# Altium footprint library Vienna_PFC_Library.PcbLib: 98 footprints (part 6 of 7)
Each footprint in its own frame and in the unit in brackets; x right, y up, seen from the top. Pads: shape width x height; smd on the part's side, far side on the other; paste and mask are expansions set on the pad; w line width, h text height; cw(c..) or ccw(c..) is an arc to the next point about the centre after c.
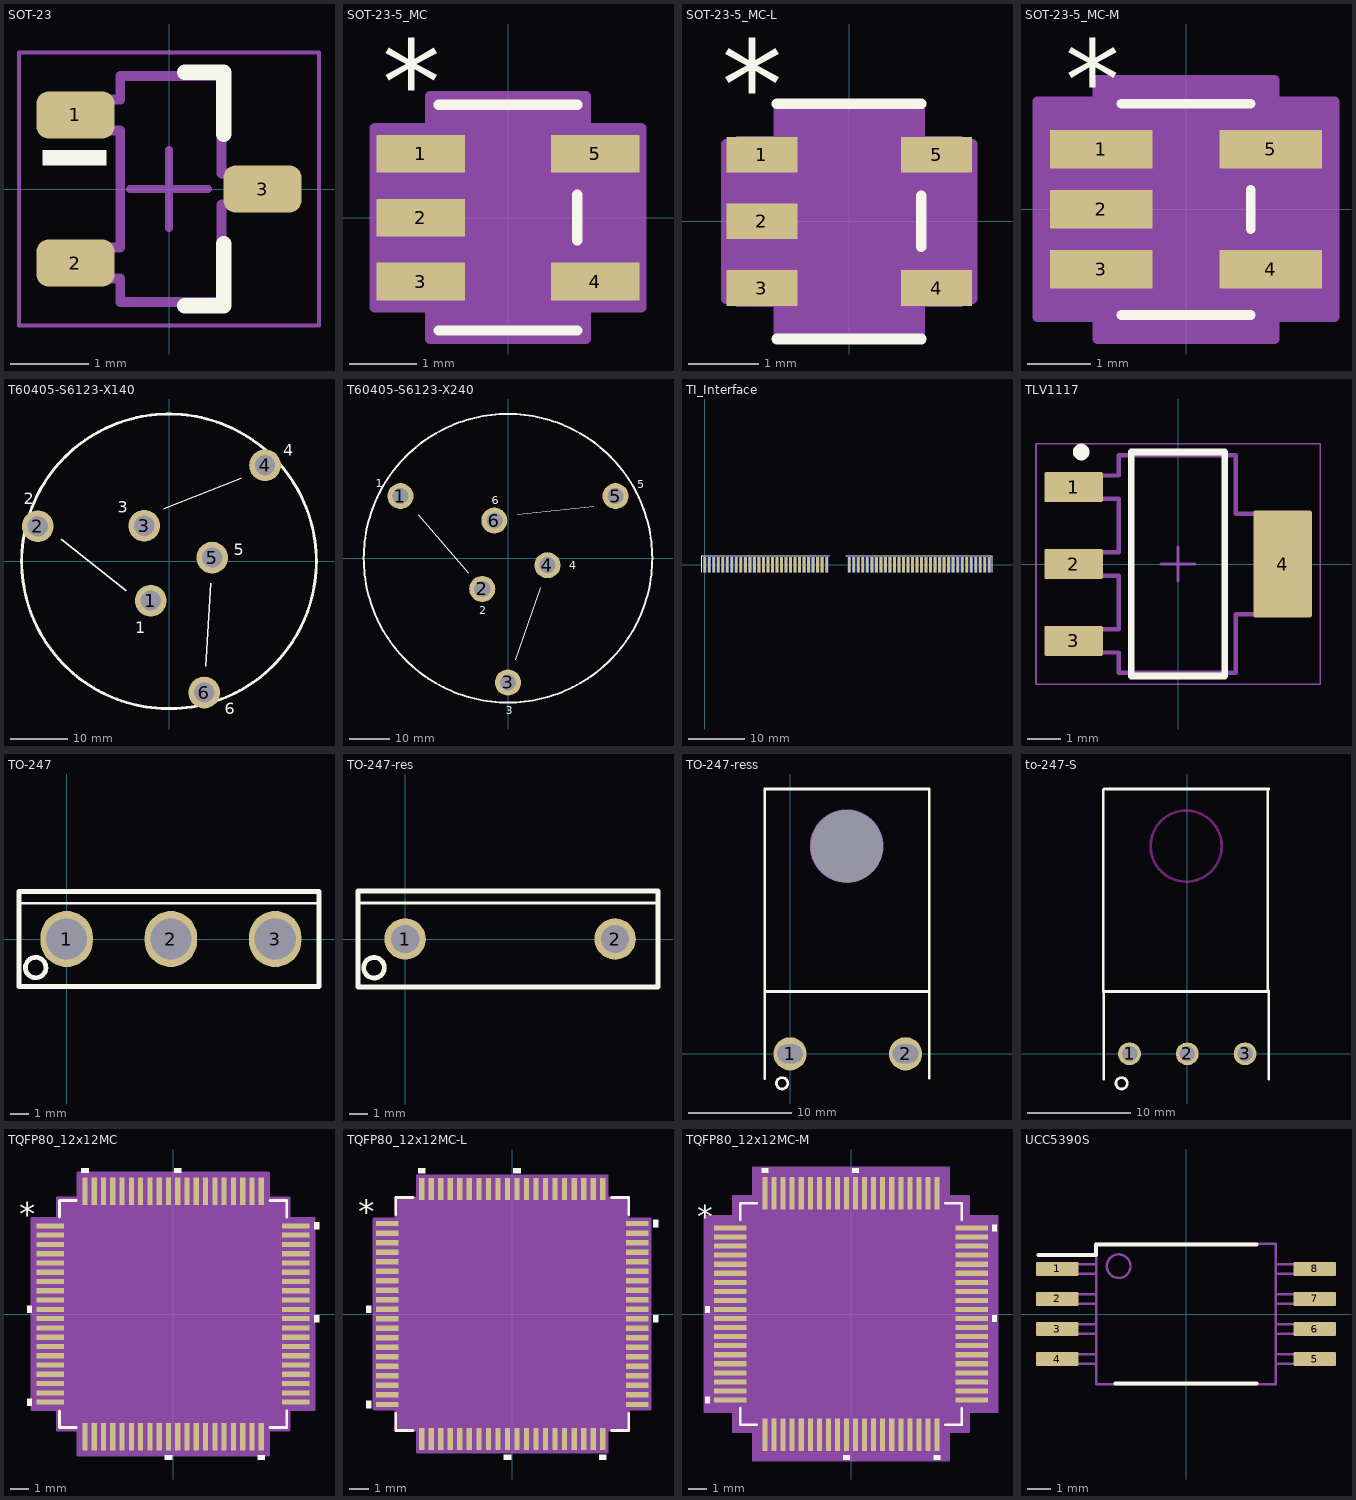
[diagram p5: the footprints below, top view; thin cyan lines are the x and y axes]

## SOT-23 [mm] "SOT23, 3-Leads, Body 2.9x1.3mm, Pitch 0.95mm, Lead Span 2.5mm, IPC Medium Density"
height 1.1
pads (3):
  rrect50% 1x0.6 smd: 1(-1.2,0.95) 2(-1.2,-0.95) 3(1.2,0)
Top Overlay:
  rectangle: -1.625,0.3 -0.8,0.5
  lines w0.2: 0.2,-1.5 0.7,-1.5 0.7,-0.7 ; 0.2,1.5 0.7,1.5 0.7,0.7
Mechanical 5:
  lines w0.127: -1.16,-1.15 -1.16,-0.75 -0.625,-0.75 -0.625,0.75 -1.16,0.75 -1.16,1.15 -0.625,1.15 -0.625,1.45 0.675,1.45 0.675,0.2 1.21,0.2 1.21,-0.2 0.675,-0.2 0.675,-1.45 -0.625,-1.45 -0.625,-1.15 -1.16,-1.15
Mechanical 15:
  lines w0.05: -1.925,-1.75 1.925,-1.75 1.925,1.75 -1.925,1.75 -1.925,-1.75
  lines w0.1: -0.5,0 0.5,0 ; 0,-0.5 0,0.5
3D body "SW3dPS-sot-3p290x130ll237h100.STEP": height 1, standoff 0, extent -1.16,-1.45 1.21,1.45

## SOT-23-5_MC [mil]
pads (5):
  rect 52x22 smd paste+0 mask+0: 1(-51,37.4) 2(-51,0) 3(-51,-37.4) 4(51,-37.4) 5(51,37.4)
Top Overlay:
  lines w6: -40.5,-66 40.5,-66 ; -40.5,66 40.5,66 ; 40.5,-13.3 40.5,13.3
  text "*" at -73.5,54.4 h50
Mechanical 13:
  lines w0: -12,61 ccw(c0,61) 12,61
  lines w1: -63,-47.4 -35.5,-47.4 -35.5,-27.4 -63,-27.4 -63,-47.4 ; -63,-10 -35.5,-10 -35.5,10 -63,10 -63,-10 ; -63,27.4 -35.5,27.4 -35.5,47.4 -63,47.4 -63,27.4 ; -35.5,-61 -35.5,61 35.5,61 35.5,-61 -35.5,-61 ; 35.5,-47.4 63,-47.4 63,-27.4 35.5,-27.4 35.5,-47.4 ; 35.5,27.4 63,27.4 63,47.4 35.5,47.4 35.5,27.4
  text "*" at -38,16.4 h50
Mechanical 15:
  region: 45.5,-71 -45.5,-71 -45.5,-52.4 -78,-52.4 -78,52.4 -45.5,52.4 -45.5,71 45.5,71 45.5,52.4 78,52.4 78,-52.4 45.5,-52.4
  lines w6: -78,-52.4 -78,52.4 -45.5,52.4 -45.5,71 45.5,71 45.5,52.4 78,52.4 78,-52.4 45.5,-52.4 45.5,-71 -45.5,-71 -45.5,-52.4 -78,-52.4
3D body: height 10, standoff 0, extent 0,0 10,10

## SOT-23-5_MC-L [mil]
pads (5):
  rect 40x20 smd paste+0 mask+0: 1(-49,37.4) 2(-49,0) 3(-49,-37.4) 4(49,-37.4) 5(49,37.4)
Top Overlay:
  lines w6: -40.5,-66 40.5,-66 ; -40.5,66 40.5,66 ; 40.5,-14.3 40.5,14.3
  text "*" at -71.5,52.4 h50
Mechanical 13:
  lines w0: -12,61 ccw(c0,61) 12,61
  lines w1: -63,-47.4 -63,-27.4 -35.5,-27.4 -35.5,-47.4 -63,-47.4 ; -63,-10 -63,10 -35.5,10 -35.5,-10 -63,-10 ; -63,27.4 -63,47.4 -35.5,47.4 -35.5,27.4 -63,27.4 ; -35.5,-61 35.5,-61 35.5,61 -35.5,61 -35.5,-61 ; 35.5,-47.4 35.5,-27.4 63,-27.4 63,-47.4 35.5,-47.4 ; 35.5,27.4 35.5,47.4 63,47.4 63,27.4 35.5,27.4
  text "*" at -38,14.4 h50
Mechanical 15:
  region: 39.5,-65 -39.5,-65 -39.5,-43.4 -69,-43.4 -69,43.4 -39.5,43.4 -39.5,65 39.5,65 39.5,43.4 69,43.4 69,-43.4 39.5,-43.4
  lines w6: -69,-43.4 -39.5,-43.4 -39.5,-65 39.5,-65 39.5,-43.4 69,-43.4 69,43.4 39.5,43.4 39.5,65 -39.5,65 -39.5,43.4 -69,43.4 -69,-43.4
3D body: height 10, standoff 0, extent 0,0 10,10

## SOT-23-5_MC-M [mil]
pads (5):
  rect 64x24 smd paste+0 mask+0: 1(-53,37.4) 2(-53,0) 3(-53,-37.4) 4(53,-37.4) 5(53,37.4)
Top Overlay:
  lines w6: -40.5,-66 40.5,-66 ; -40.5,66 40.5,66 ; 40.5,-12.3 40.5,12.3
  text "*" at -75.5,56.4 h50
Mechanical 13:
  lines w0: -12,61 ccw(c0,61) 12,61
  lines w1: -63,-47.4 -63,-27.4 -35.5,-27.4 -35.5,-47.4 -63,-47.4 ; -63,-10 -63,10 -35.5,10 -35.5,-10 -63,-10 ; -63,27.4 -63,47.4 -35.5,47.4 -35.5,27.4 -63,27.4 ; -35.5,-61 35.5,-61 35.5,61 -35.5,61 -35.5,-61 ; 35.5,-47.4 35.5,-27.4 63,-27.4 63,-47.4 35.5,-47.4 ; 35.5,27.4 35.5,47.4 63,47.4 63,27.4 35.5,27.4
  text "*" at -38,18.4 h50
Mechanical 15:
  region: 55.5,-81 -55.5,-81 -55.5,-67.4 -93,-67.4 -93,67.4 -55.5,67.4 -55.5,81 55.5,81 55.5,67.4 93,67.4 93,-67.4 55.5,-67.4
  lines w6: -93,-67.4 -55.5,-67.4 -55.5,-81 55.5,-81 55.5,-67.4 93,-67.4 93,67.4 55.5,67.4 55.5,81 -55.5,81 -55.5,67.4 -93,67.4 -93,-67.4
3D body: height 10, standoff 0, extent 0,0 10,10

## T60405-S6123-X140 [mm] "Common mode choke"
height 33
pads (6):
  round 5.5 hole 3.5: 1(-3.17,-6.797) 2(-22.699,6.082) 3(-4.302,6.144) 4(16.617,16.617) 5(7.471,0.654) 6(6.082,-22.699)
Top Overlay:
  circle w0.5: c0,0 r25.5
  lines w0.254: -18.625,3.866 -7.366,-5.08 ; -0.868,9.126 12.509,14.404 ; 6.328,-18.16 7.199,-3.805
  text "2" at -25.146,9.906 h2
  text "4" at 19.812,18.288 h2
  text "6" at 9.652,-26.416 h2
  text "3" at -8.89,8.382 h2
  text "5" at 11.176,1.016 h2
  text "1" at -5.842,-12.446 h2
3D body "6123-X140 3D Model.stp": height 32, standoff -5.5, extent -25.905,-26.164 26.092,25.834

## T60405-S6123-X240 [mm] "Common mode choke"
height 37
pads (6):
  round 6.5 hole 4: 1(-26.847,15.5) 2(-6.428,-7.66) 3(0,-31) 4(9.848,-1.736) 5(26.847,15.5) 6(-3.42,9.397)
Top Overlay:
  circle w0.5: c0,0 r36
  lines w0.254: -22.339,10.815 -9.906,-3.556 ; 1.899,-25.319 8.128,-7.366 ; 2.432,11.012 21.336,12.954
  text "1" at -33.02,17.78 h2
  text "5" at 32.258,17.526 h2
  text "3" at -0.508,-38.862 h2
  text "6" at -4.064,13.462 h2
  text "4" at 15.24,-2.794 h2
  text "2" at -7.112,-13.97 h2
3D body "T60405-S6123-X240.stp": height 36, standoff -5.5, extent -34.967,-34.967 34.917,34.901

## TI_Interface [mm]
pads (120):
  rect 0.5x2.724 smd: 1(0,0) 3(0.8,0) 5(1.6,0) 7(2.4,0) 9(3.2,0) 11(4,0) 13(4.8,0) 15(5.6,0) 17(6.4,0) 19(7.2,0) 21(8,0) 23(8.8,0) 25(9.6,0) 27(10.4,0) 29(11.2,0) 31(12,0) 33(12.8,0) 35(13.6,0) 37(14.4,0) 39(15.2,0) 41(16,0) 43(16.8,0) 45(17.6,0) 47(18.4,0) 49(19.2,0) 51(20,0) 53(20.8,0) 55(21.6,0) 57(25.6,0) 59(26.4,0) 61(27.2,0) 63(28,0) 65(28.8,0) 67(29.6,0) 69(30.4,0) 71(31.2,0) 73(32,0) 75(32.8,0) 77(33.6,0) 79(34.4,0) 81(35.2,0) 83(36,0) 85(36.8,0) 87(37.6,0) 89(38.4,0) 91(39.2,0) 93(40,0) 95(40.8,0) 97(41.6,0) 99(42.4,0) 101(43.2,0) 103(44,0) 105(44.8,0) 107(45.6,0) 109(46.4,0) 111(47.2,0) 113(48,0) 115(48.8,0) 117(49.6,0) 119(50.4,0)
  rect 0.5x2.724 smd far side: 2(0,0) 4(0.8,0) 6(1.6,0) 8(2.4,0) 10(3.2,0) 12(4,0) 14(4.8,0) 16(5.6,0) 18(6.4,0) 20(7.2,0) 22(8,0) 24(8.801,0) 26(9.6,0) 28(10.4,0) 30(11.2,0) 32(12,0) 34(12.802,0) 36(13.602,0) 38(14.402,0) 40(15.202,0) 42(16.002,0) 44(16.8,0) 46(17.602,0) 48(18.4,0) 50(19.202,0) 52(20.002,0) 54(20.803,0) 56(21.6,0) 58(25.6,0) 60(26.4,0) 62(27.2,0) 64(28,0) 66(28.8,0) 68(29.6,0) 70(30.4,0) 72(31.2,0) 74(32,0) 76(32.801,0) 78(33.601,0) 80(34.401,0) 82(35.201,0) 84(36.001,0) 86(36.801,0) 88(37.601,0) 90(38.401,0) 92(39.201,0) 94(40.001,0) 96(40.802,0) 98(41.602,0) 100(42.402,0) 102(43.202,0) 104(44.002,0) 106(44.802,0) 108(45.602,0) 110(46.402,0) 112(47.202,0) 114(48.002,0) 116(48.803,0) 118(49.603,0) 120(50.403,0)
Top Overlay:
  lines w0.1: -0.5,-1.38 -0.5,1.6 22.1,1.6 ; 25,1.6 50.925,1.6 ; 50.9,-1.38 50.9,1.6

## TLV1117 [mm] "SOT223/SC73, 4-Leads, Body 6.5x3.5mm, Pitch 2.3mm, Lead Span 7mm, IPC Medium Density"
height 1.8
pads (4):
  rrect11% 1.75x0.9 smd: 1(-3.125,2.3) 2(-3.125,0) 3(-3.125,-2.3)
  rrect6% 1.75x3.2 smd: 4(3.125,0)
Top Overlay:
  circle w0.25: c-2.9,3.35 r0.125
  lines w0.2: -1.4,-3.35 1.4,-3.35 1.4,3.35 -1.4,3.35 -1.4,-3.35
Mechanical 5:
  lines w0.127: -3.525,-2.65 -2.797,-2.65 -2.612,-2.65 -2.374,-2.65 -2.003,-2.65 -1.775,-2.65 -1.775,-3.25 1.725,-3.25 1.725,-1.5 1.953,-1.5 2.324,-1.5 2.562,-1.5 2.747,-1.5 3.475,-1.5 3.475,1.5 2.747,1.5 2.562,1.5 2.324,1.5 1.953,1.5 1.725,1.5 1.725,3.25 -1.775,3.25 -1.775,2.65 -2.003,2.65 -2.374,2.65 -2.612,2.65 -2.797,2.65 -3.525,2.65 -3.525,1.95 -2.797,1.95 -2.612,1.95 -2.374,1.95 -2.003,1.95 -1.775,1.95 -1.775,0.35 -2.003,0.35 -2.374,0.35 -2.612,0.35 -2.797,0.35 -3.525,0.35 -3.525,-0.35 -2.797,-0.35 -2.612,-0.35 -2.374,-0.35 -2.003,-0.35 -1.775,-0.35 -1.775,-1.95 -2.003,-1.95 -2.374,-1.95 -2.612,-1.95 -2.797,-1.95 -3.525,-1.95 -3.525,-2.65
Mechanical 15:
  lines w0.05: -4.25,-3.6 -4.25,3.6 4.25,3.6 4.25,-3.6 -4.25,-3.6
  lines w0.1: -0.5,0 0.5,0 ; 0,-0.5 0,0.5
3D body "DCY0004A.stp": height 1.68, standoff 0, extent -3.48,-3.25 3.48,3.25

## TO-247 [mm]
pads (3):
  oval 2.8x3 hole 2.2: 1(0,0) 2(5.563,0) 3(11.125,0)
Top Overlay:
  lines w0.152: -2.413,1.905 13.335,1.905
  lines w0.254: -2.159,-1.321 ccw(c-1.651,-1.524) -2.106,-1.221 ; -2.54,-2.54 13.462,-2.54 13.462,2.54 -2.54,2.54 -2.54,-2.54
3D body "User Library-TO-247.STEP": height 20.33, standoff -15.73, extent -2.159,-2.667 13.081,1.905

## TO-247-res [mm]
pads (2):
  round 2.2 hole 1.5: 1(0,0) 2(11.125,0)
Top Overlay:
  lines w0.152: -2.413,1.905 13.335,1.905
  lines w0.254: -2.159,-1.321 ccw(c-1.651,-1.524) -2.106,-1.221 ; -2.5,-2.54 13.4,-2.54 13.4,2.54 -2.5,2.54 -2.5,-2.54

## TO-247-ress [mm]
pads (3):
  round 0 hole 7: 0(5.45,20)
  round 3.2 hole 1.8 slot 2.5 at 0 deg: 1(0,0) 2(11.125,0)
Top Overlay:
  lines w0.254: -2.44,-2.388 -2.44,6.014 -2.44,25.5 13.411,25.5 13.4,25.489 13.4,6.085 13.4,2.743 13.4,-2.338 ; -2.337,5.994 13.31,5.994 ; -1.272,-2.64 ccw(c-0.764,-2.843) -1.219,-2.54
Mechanical 1:
  circle w0.254: c5.45,20 r3.423
3D body "Diode.STEP": height 5.26, standoff -9.24, extent -2.489,-0.504 13.411,25.396

## to-247-S [mm]
pads (3):
  round 2.2 hole 1.5: 1(-5.563,0) 2(0,0) 3(5.563,0)
Top Overlay:
  lines w0.254: -8.063,-2.438 -8.063,2.642 ; -8.063,2.54 -8.063,5.954 -8.103,5.994 -8.103,25.4 -8.003,25.5 ; -7.899,5.994 7.747,5.994 ; -7.798,25.5 7.849,25.5 7.747,25.398 7.747,5.994 ; -6.835,-2.64 ccw(c-6.327,-2.843) -6.782,-2.54 ; 7.837,-2.438 7.837,2.743 7.837,6.085 7.747,5.994
Keep-Out Layer:
  circle w0.254: c-0.113,20 r3.423

## TQFP80_12x12MC [mil]
pads (80):
  rect 58x11 smd paste+0 mask+0: 1(-260.5,187.01) 2(-260.5,167.32) 3(-260.5,147.64) 4(-260.5,127.95) 5(-260.5,108.27) 6(-260.5,88.58) 7(-260.5,68.9) 8(-260.5,49.21) 9(-260.5,29.53) 10(-260.5,9.84) 11(-260.5,-9.84) 12(-260.5,-29.53) 13(-260.5,-49.21) 14(-260.5,-68.9) 15(-260.5,-88.58) 16(-260.5,-108.27) 17(-260.5,-127.95) 18(-260.5,-147.64) 19(-260.5,-167.32) 20(-260.5,-187.01) 41(260.5,-187.01) 42(260.5,-167.32) 43(260.5,-147.64) 44(260.5,-127.95) 45(260.5,-108.27) 46(260.5,-88.58) 47(260.5,-68.9) 48(260.5,-49.21) 49(260.5,-29.53) 50(260.5,-9.84) 51(260.5,9.84) 52(260.5,29.53) 53(260.5,49.21) 54(260.5,68.9) 55(260.5,88.58) 56(260.5,108.27) 57(260.5,127.95) 58(260.5,147.64) 59(260.5,167.32) 60(260.5,187.01)
  rect 11x58 smd paste+0 mask+0: 21(-187.01,-260.5) 22(-167.32,-260.5) 23(-147.64,-260.5) 24(-127.95,-260.5) 25(-108.27,-260.5) 26(-88.58,-260.5) 27(-68.9,-260.5) 28(-49.21,-260.5) 29(-29.53,-260.5) 30(-9.84,-260.5) 31(9.84,-260.5) 32(29.53,-260.5) 33(49.21,-260.5) 34(68.9,-260.5) 35(88.58,-260.5) 36(108.27,-260.5) 37(127.95,-260.5) 38(147.64,-260.5) 39(167.32,-260.5) 40(187.01,-260.5) 61(187.01,260.5) 62(167.32,260.5) 63(147.64,260.5) 64(127.95,260.5) 65(108.27,260.5) 66(88.58,260.5) 67(68.9,260.5) 68(49.21,260.5) 69(29.53,260.5) 70(9.84,260.5) 71(-9.84,260.5) 72(-29.53,260.5) 73(-49.21,260.5) 74(-68.9,260.5) 75(-88.58,260.5) 76(-108.27,260.5) 77(-127.95,260.5) 78(-147.64,260.5) 79(-167.32,260.5) 80(-187.01,260.5)
Top Overlay:
  region: -299.5,17.34 -309.5,17.34 -309.5,2.34 -299.5,2.34
  region: -299.5,-179.51 -309.5,-179.51 -309.5,-194.51 -299.5,-194.51
  region: -2.34,-299.5 -17.34,-299.5 -17.34,-309.5 -2.34,-309.5
  region: 194.51,-299.5 179.51,-299.5 179.51,-309.5 194.51,-309.5
  region: 299.5,-2.34 309.5,-2.34 309.5,-17.34 299.5,-17.34
  region: 299.5,194.51 309.5,194.51 309.5,179.51 299.5,179.51
  region: 17.34,299.5 2.34,299.5 2.34,309.5 17.34,309.5
  region: -179.51,299.5 -194.51,299.5 -194.51,309.5 -179.51,309.5
  lines w6: -241,-205.61 -241,-241 -205.61,-241 ; -241,205.61 -241,241 -205.61,241 ; 205.61,-241 241,-241 241,-205.61 ; 205.61,241 241,241 241,205.61
  text "*" at -327,186.85 h50
Mechanical 13:
  drawing of 325 lines, arcs and shapes, not listed
  text "*" at -233.5,171.85 h50
Mechanical 15:
  region: -202.51,-246 -246,-246 -246,-202.51 -299.5,-202.51 -299.5,202.51 -246,202.51 -246,246 -202.51,246 -202.51,299.5 202.51,299.5 202.51,246 246,246 246,202.51 299.5,202.51 299.5,-202.51 246,-202.51 246,-246 202.51,-246 202.51,-299.5 -202.51,-299.5
  lines w6: -299.5,-202.51 -246,-202.51 -246,-246 -202.51,-246 -202.51,-299.5 202.51,-299.5 202.51,-246 246,-246 246,-202.51 299.5,-202.51 299.5,202.51 246,202.51 246,246 202.51,246 202.51,299.5 -202.51,299.5 -202.51,246 -246,246 -246,202.51 -299.5,202.51 -299.5,-202.51
3D body: height 10, standoff 0, extent 0,0 10,10

## TQFP80_12x12MC-L [mil]
pads (80):
  rect 46x11 smd paste+0 mask+0: 1(-258.5,187.01) 2(-258.5,167.32) 3(-258.5,147.64) 4(-258.5,127.95) 5(-258.5,108.27) 6(-258.5,88.58) 7(-258.5,68.9) 8(-258.5,49.21) 9(-258.5,29.53) 10(-258.5,9.84) 11(-258.5,-9.84) 12(-258.5,-29.53) 13(-258.5,-49.21) 14(-258.5,-68.9) 15(-258.5,-88.58) 16(-258.5,-108.27) 17(-258.5,-127.95) 18(-258.5,-147.64) 19(-258.5,-167.32) 20(-258.5,-187.01) 41(258.5,-187.01) 42(258.5,-167.32) 43(258.5,-147.64) 44(258.5,-127.95) 45(258.5,-108.27) 46(258.5,-88.58) 47(258.5,-68.9) 48(258.5,-49.21) 49(258.5,-29.53) 50(258.5,-9.84) 51(258.5,9.84) 52(258.5,29.53) 53(258.5,49.21) 54(258.5,68.9) 55(258.5,88.58) 56(258.5,108.27) 57(258.5,127.95) 58(258.5,147.64) 59(258.5,167.32) 60(258.5,187.01)
  rect 11x46 smd paste+0 mask+0: 21(-187.01,-258.5) 22(-167.32,-258.5) 23(-147.64,-258.5) 24(-127.95,-258.5) 25(-108.27,-258.5) 26(-88.58,-258.5) 27(-68.9,-258.5) 28(-49.21,-258.5) 29(-29.53,-258.5) 30(-9.84,-258.5) 31(9.84,-258.5) 32(29.53,-258.5) 33(49.21,-258.5) 34(68.9,-258.5) 35(88.58,-258.5) 36(108.27,-258.5) 37(127.95,-258.5) 38(147.64,-258.5) 39(167.32,-258.5) 40(187.01,-258.5) 61(187.01,258.5) 62(167.32,258.5) 63(147.64,258.5) 64(127.95,258.5) 65(108.27,258.5) 66(88.58,258.5) 67(68.9,258.5) 68(49.21,258.5) 69(29.53,258.5) 70(9.84,258.5) 71(-9.84,258.5) 72(-29.53,258.5) 73(-49.21,258.5) 74(-68.9,258.5) 75(-88.58,258.5) 76(-108.27,258.5) 77(-127.95,258.5) 78(-147.64,258.5) 79(-167.32,258.5) 80(-187.01,258.5)
Top Overlay:
  region: -291.5,17.34 -301.5,17.34 -301.5,2.34 -291.5,2.34
  region: -291.5,-179.51 -301.5,-179.51 -301.5,-194.51 -291.5,-194.51
  region: -2.34,-291.5 -17.34,-291.5 -17.34,-301.5 -2.34,-301.5
  region: 194.51,-291.5 179.51,-291.5 179.51,-301.5 194.51,-301.5
  region: 291.5,-2.34 301.5,-2.34 301.5,-17.34 291.5,-17.34
  region: 291.5,194.51 301.5,194.51 301.5,179.51 291.5,179.51
  region: 17.34,291.5 2.34,291.5 2.34,301.5 17.34,301.5
  region: -179.51,291.5 -194.51,291.5 -194.51,301.5 -179.51,301.5
  lines w6: -241,-205.61 -241,-241 -205.61,-241 ; -241,205.61 -241,241 -205.61,241 ; 205.61,-241 241,-241 241,-205.61 ; 205.61,241 241,241 241,205.61
  text "*" at -319,186.85 h50
Mechanical 13:
  drawing of 325 lines, arcs and shapes, not listed
  text "*" at -233.5,171.85 h50
Mechanical 15:
  region: -196.51,-240 -240,-240 -240,-196.51 -285.5,-196.51 -285.5,196.51 -240,196.51 -240,240 -196.51,240 -196.51,285.5 196.51,285.5 196.51,240 240,240 240,196.51 285.5,196.51 285.5,-196.51 240,-196.51 240,-240 196.51,-240 196.51,-285.5 -196.51,-285.5
  lines w6: -285.5,-196.51 -240,-196.51 -240,-240 -196.51,-240 -196.51,-285.5 196.51,-285.5 196.51,-240 240,-240 240,-196.51 285.5,-196.51 285.5,196.51 240,196.51 240,240 196.51,240 196.51,285.5 -196.51,285.5 -196.51,240 -240,240 -240,196.51 -285.5,196.51 -285.5,-196.51
3D body: height 10, standoff 0, extent 0,0 10,10

## TQFP80_12x12MC-M [mil]
pads (80):
  rect 70x11 smd paste+0 mask+0: 1(-262.5,187.01) 2(-262.5,167.32) 3(-262.5,147.64) 4(-262.5,127.95) 5(-262.5,108.27) 6(-262.5,88.58) 7(-262.5,68.9) 8(-262.5,49.21) 9(-262.5,29.53) 10(-262.5,9.84) 11(-262.5,-9.84) 12(-262.5,-29.53) 13(-262.5,-49.21) 14(-262.5,-68.9) 15(-262.5,-88.58) 16(-262.5,-108.27) 17(-262.5,-127.95) 18(-262.5,-147.64) 19(-262.5,-167.32) 20(-262.5,-187.01) 41(262.5,-187.01) 42(262.5,-167.32) 43(262.5,-147.64) 44(262.5,-127.95) 45(262.5,-108.27) 46(262.5,-88.58) 47(262.5,-68.9) 48(262.5,-49.21) 49(262.5,-29.53) 50(262.5,-9.84) 51(262.5,9.84) 52(262.5,29.53) 53(262.5,49.21) 54(262.5,68.9) 55(262.5,88.58) 56(262.5,108.27) 57(262.5,127.95) 58(262.5,147.64) 59(262.5,167.32) 60(262.5,187.01)
  rect 11x70 smd paste+0 mask+0: 21(-187.01,-262.5) 22(-167.32,-262.5) 23(-147.64,-262.5) 24(-127.95,-262.5) 25(-108.27,-262.5) 26(-88.58,-262.5) 27(-68.9,-262.5) 28(-49.21,-262.5) 29(-29.53,-262.5) 30(-9.84,-262.5) 31(9.84,-262.5) 32(29.53,-262.5) 33(49.21,-262.5) 34(68.9,-262.5) 35(88.58,-262.5) 36(108.27,-262.5) 37(127.95,-262.5) 38(147.64,-262.5) 39(167.32,-262.5) 40(187.01,-262.5) 61(187.01,262.5) 62(167.32,262.5) 63(147.64,262.5) 64(127.95,262.5) 65(108.27,262.5) 66(88.58,262.5) 67(68.9,262.5) 68(49.21,262.5) 69(29.53,262.5) 70(9.84,262.5) 71(-9.84,262.5) 72(-29.53,262.5) 73(-49.21,262.5) 74(-68.9,262.5) 75(-88.58,262.5) 76(-108.27,262.5) 77(-127.95,262.5) 78(-147.64,262.5) 79(-167.32,262.5) 80(-187.01,262.5)
Top Overlay:
  region: -307.5,17.34 -317.5,17.34 -317.5,2.34 -307.5,2.34
  region: -307.5,-179.51 -317.5,-179.51 -317.5,-194.51 -307.5,-194.51
  region: -2.34,-307.5 -17.34,-307.5 -17.34,-317.5 -2.34,-317.5
  region: 194.51,-307.5 179.51,-307.5 179.51,-317.5 194.51,-317.5
  region: 307.5,-2.34 317.5,-2.34 317.5,-17.34 307.5,-17.34
  region: 307.5,194.51 317.5,194.51 317.5,179.51 307.5,179.51
  region: 17.34,307.5 2.34,307.5 2.34,317.5 17.34,317.5
  region: -179.51,307.5 -194.51,307.5 -194.51,317.5 -179.51,317.5
  lines w6: -241,-205.61 -241,-241 -205.61,-241 ; -241,205.61 -241,241 -205.61,241 ; 205.61,-241 241,-241 241,-205.61 ; 205.61,241 241,241 241,205.61
  text "*" at -335,186.85 h50
Mechanical 13:
  drawing of 325 lines, arcs and shapes, not listed
  text "*" at -233.5,171.85 h50
Mechanical 15:
  region: -212.51,-256 -256,-256 -256,-212.51 -317.5,-212.51 -317.5,212.51 -256,212.51 -256,256 -212.51,256 -212.51,317.5 212.51,317.5 212.51,256 256,256 256,212.51 317.5,212.51 317.5,-212.51 256,-212.51 256,-256 212.51,-256 212.51,-317.5 -212.51,-317.5
  lines w6: -317.5,-212.51 -256,-212.51 -256,-256 -212.51,-256 -212.51,-317.5 212.51,-317.5 212.51,-256 256,-256 256,-212.51 317.5,-212.51 317.5,212.51 256,212.51 256,256 212.51,256 212.51,317.5 -212.51,317.5 -212.51,256 -256,256 -256,212.51 -317.5,212.51 -317.5,-212.51
3D body: height 10, standoff 0, extent 0,0 10,10

## UCC5390S [mm] "SOIC, 8-Leads, Body 5.95x7.6mm (max), Pitch 1.27mm"
height 2.8
pads (8):
  rrect17% 1.8x0.6 smd: 1(-5.45,1.905) 2(-5.45,0.635) 3(-5.45,-0.635) 4(-5.45,-1.905) 5(5.45,-1.905) 6(5.45,-0.635) 7(5.45,0.635) 8(5.45,1.905)
Top Overlay:
  lines w0.17: -6.25,2.5 -3.8,2.5 -3.8,2.95 2.975,2.95 ; -2.975,-2.95 2.975,-2.95
Mechanical 5:
  circle w0.1: c-2.85,2.025 r0.5
  lines w0.1: -3.805,-2.105 -5.8,-2.105 -5.8,-1.705 -3.805,-1.705 ; -3.805,-0.835 -5.8,-0.835 -5.8,-0.435 -3.805,-0.435 ; -3.805,0.435 -5.8,0.435 -5.8,0.835 -3.805,0.835 ; -3.805,1.705 -5.8,1.705 -5.8,2.105 -3.805,2.105 ; 3.805,-2.105 5.8,-2.105 5.8,-1.705 3.805,-1.705 ; 3.805,-0.835 5.8,-0.835 5.8,-0.435 3.805,-0.435 ; 3.805,0.435 5.8,0.435 5.8,0.835 3.805,0.835 ; 3.805,1.705 5.8,1.705 5.8,2.105 3.805,2.105 ; -3.8,-2.975 -3.8,2.975 3.8,2.975 3.8,-2.975 -3.8,-2.975
3D body "DWV0008A.stp": height 2.67, standoff -0.03, extent -5.768,-2.925 5.768,2.925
